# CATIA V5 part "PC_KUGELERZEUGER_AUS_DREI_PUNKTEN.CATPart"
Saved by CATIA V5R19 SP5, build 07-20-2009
Part number: PC_KUGELERZEUGER_AUS_DREI_PUNKTEN
Bounding box of the stored display mesh (mm): x -13.739 to 39.739, y -1.739 to 51.739, z -17.739 to 35.739
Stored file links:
  S:\Stadler\SUPER_USER\SU_SCHULUNGEN\weitere_PC\PC_KUGELERZEUGER_AUS_DREI_PUNKTEN.CATPart
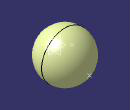
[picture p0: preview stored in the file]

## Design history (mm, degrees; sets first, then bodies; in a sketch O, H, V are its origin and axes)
Set1 "INPUT"
  Point1: (10, 0, 0)
  Point2: (10, 50, 0)
  Point3: (20, 40, 30)
Set2 "POWER_COPY"
  Circle1: type 3Points, Start 0, End 180, Element1 Point1, Element2 Point2, Element3 Point3
  Point4 "MITTELPUNKT": type Center, Curve Circle1
  Sphere1: Center Point4, Radius 26.7395 {= RADIUS}, Angle1 -45, Angle3 0, Angle4 180
Body1 (main body)
Relations
  RADIUS = distance(Point4 ,Point1 )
